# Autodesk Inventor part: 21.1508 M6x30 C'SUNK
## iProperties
Created: 2006-12
Part Number: 21.1508 M6x30 C'SUNK
Material: Steel, Mild
Description: Hexagon socket countersunk head cap screws
Document SubType Name: Modeling
Standard: DIN 7991
Designer: Andy Moles
Standards Organization: DIN
Language: en-US
Size Designation: M6x30
Categories: <MemberInstance Version="R10.0.0"><Categories><Category DisplayName="Fasteners" InternalName="e4da775c-781d-43d5-af7c-5136215cf5a6" Mnemonic="FSTN"><Category Di
Density: 7.86 g/cm^3
Mass: 7.46657 g
Surface Area: 8.04484 cm^2
Volume: 0.949945 cm^3
Author: Andy Moles
Revision Number: 1
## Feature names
1. Revolution1
2. Extrusion1
3. Fillet1
4. Chamfer1
